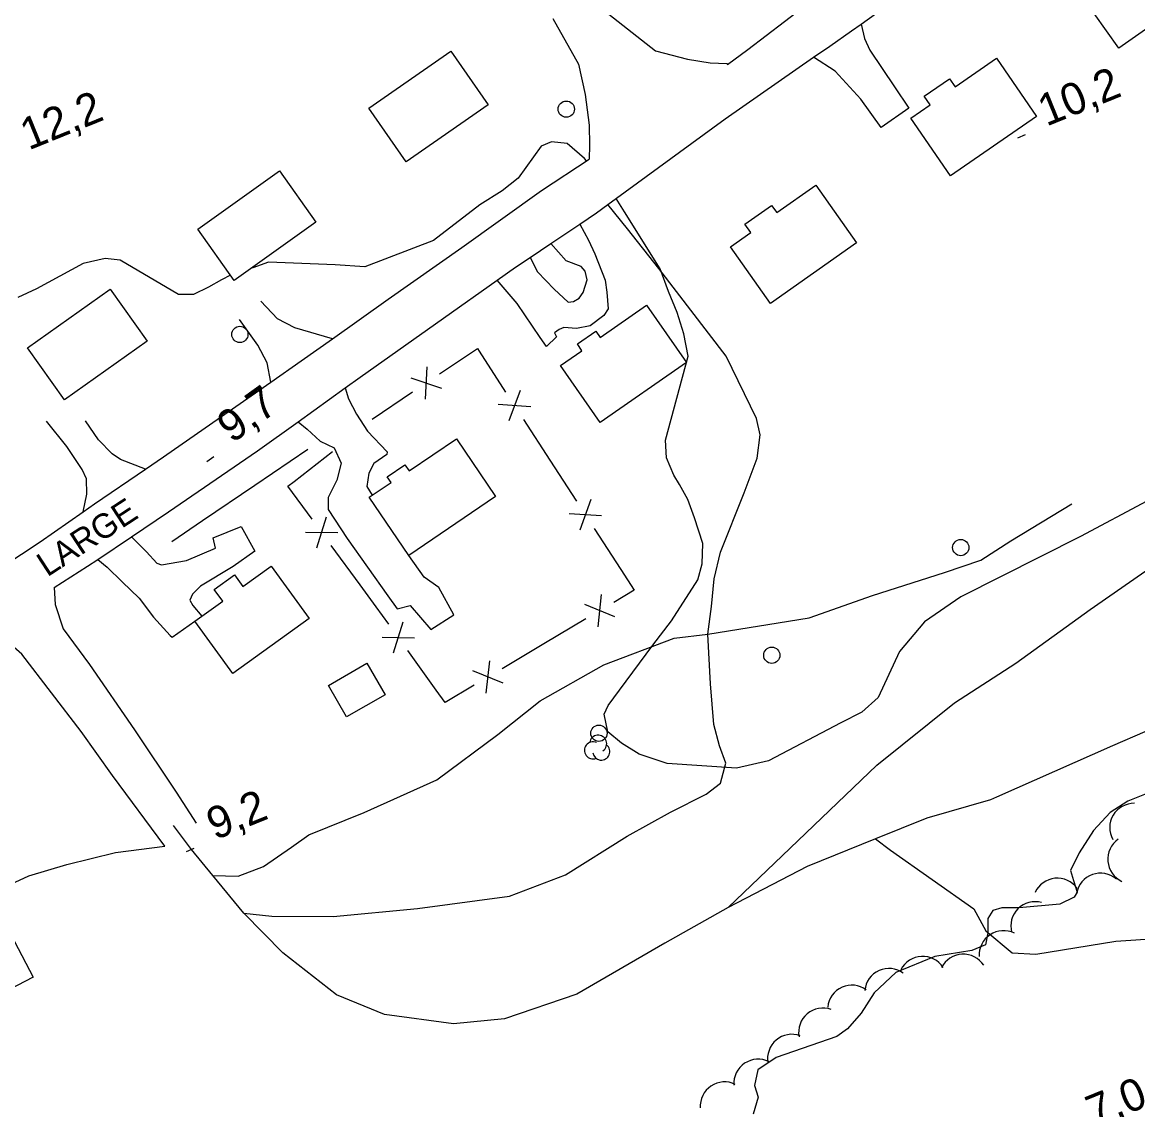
# Model space of a CAD drawing. Extents: x 362852 to 366875, y 5563573 to 5566479.
# Drawn here: x 365220.3 to 365357.5, y 5564880.3 to 5565014.2 of the extents above; entities that cross this region are included whole.
import ezdxf

# ---------------------------------------------------------------- set-up
doc = ezdxf.new("R2010")
doc.units = 0
for name, color, linetype in [('Niveau 1', 7, 'Continuous'), ('Niveau 19', 7, 'Continuous'), ('Niveau 2', 7, 'Continuous'), ('Niveau 21', 7, 'Continuous'), ('Niveau 22', 7, 'Continuous'), ('Niveau 3', 7, 'Continuous'), ('Niveau 31', 7, 'Continuous'), ('Niveau 36', 7, 'Continuous'), ('Niveau 37', 7, 'Continuous'), ('Niveau 4', 7, 'Continuous'), ('Niveau 44', 7, 'Continuous')]:
    doc.layers.add(name, color=color, linetype=linetype)

msp = doc.modelspace()

# ---------------------------------------------------------------- linework, layer by layer
at = {"layer": 'Niveau 1'}
for points in [[(365289.71, 5564997.1), (365289.45, 5564997.4), (365287.32, 5564999.25), (365285.38, 5564999.45), (365284.1, 5564998.92), (365281.28, 5564994.98), (365279.33, 5564993.43), (365276.59, 5564991.68), (365270.85, 5564987.32), (365262.42, 5564984.08), (365258.75, 5564984.29), (365250.58, 5564984.63), (365248.63, 5564983.94), (365248.47, 5564983.89)], [(365358.63, 5564955.23), (365350.48, 5564950.88), (365335.76, 5564943.45), (365331.3, 5564940.38), (365328.2, 5564936.74), (365325.57, 5564931.06), (365323.58, 5564929.24), (365321.01, 5564927.94), (365312.1, 5564923.26), (365308.14, 5564922.36), (365299.63, 5564922.93), (365296.18, 5564924.1), (365294.02, 5564925.43), (365292.33, 5564926.84), (365291.87, 5564929), (365292.36, 5564930.07), (365293.74, 5564931.95), (365297.88, 5564937.5), (365300.17, 5564940.49), (365303.4, 5564945.55), (365303.95, 5564947.51), (365304.03, 5564950.02), (365302.97, 5564953.17), (365302.16, 5564955.44), (365301.16, 5564957.26), (365300.43, 5564958.44), (365299.56, 5564960.55), (365299.4, 5564962.72), (365302.2, 5564973.05), (365301.69, 5564975.82), (365300.85, 5564978.46), (365299.8, 5564981.01), (365298.77, 5564983.82), (365294.39, 5564990.85), (365293.34, 5564992.46)], [(365245.9, 5564983.03), (365244.79, 5564982.48), (365243.19, 5564981.57), (365241.33, 5564980.67), (365239.48, 5564980.65), (365232.31, 5564984.87), (365230.48, 5564985.1), (365227.77, 5564984.48), (365222.01, 5564981.35), (365219.73, 5564980.28)]]:
    msp.add_lwpolyline(points, dxfattribs=at)
at = {"layer": 'Niveau 19'}
for points in [[(365323.48, 5565013.92), (365323.91, 5565012.18), (365324.58, 5565010.72), (365327.61, 5565006.22), (365329.38, 5565003.59), (365325.95, 5565001.2), (365323.45, 5565004.71), (365320.3, 5565008.13), (365317.65, 5565009.85)], [(365288.89, 5564989.33), (365289.95, 5564987.34), (365290.71, 5564985.66), (365291.98, 5564982.41), (365292.21, 5564980.95), (365292.37, 5564978.9), (365291.84, 5564978.06), (365290.13, 5564976.8), (365288.46, 5564976.46), (365286.92, 5564976.58), (365286.34, 5564976.34), (365285.76, 5564975.92), (365286.01, 5564975.46), (365284.77, 5564974.26), (365284, 5564975.37), (365281.16, 5564979.54), (365278.7, 5564982.42)], [(365282.75, 5564985.22), (365283.66, 5564983.44), (365285.72, 5564981.31), (365287.43, 5564979.72), (365288.08, 5564979.8), (365288.78, 5564980.21), (365289.3, 5564980.92), (365289.78, 5564982.48), (365289.54, 5564983.51), (365289.04, 5564984.11), (365287.21, 5564984.79), (365285.32, 5564986.94)], [(365258.44, 5564975.21), (365253.8, 5564976.55), (365251.67, 5564977.67), (365249.61, 5564979.83)], [(365250.84, 5564969.86), (365250.4, 5564972.26), (365249.27, 5564974.43), (365246.99, 5564977.57)], [(365259.99, 5564969.16), (365260.43, 5564967.82), (365261.4, 5564965.92), (365262.76, 5564963.84), (365265.18, 5564961.29), (365265.13, 5564960.95), (365263.53, 5564959.86), (365262.9, 5564958.67), (365262.65, 5564957.01), (365263.33, 5564955.96)], [(365227.77, 5564953.92), (365228.21, 5564956.1), (365228.19, 5564957.96), (365227.65, 5564959.11), (365225.75, 5564961.97), (365223.24, 5564965.06)], [(365235.43, 5564959.17), (365232.36, 5564960.36), (365231.33, 5564961.06), (365229.65, 5564962.75), (365228.06, 5564965.1)], [(365254.2, 5564964.99), (365255.32, 5564964.08), (365256.91, 5564962.62), (365258.63, 5564961.79), (365259.49, 5564959.88), (365258.97, 5564957.82), (365257.91, 5564955.69), (365257.91, 5564954.21), (365260.25, 5564950.61), (365265.25, 5564943.59), (365266.4, 5564941.99), (365267.98, 5564942.37), (365270.55, 5564939.43), (365273.36, 5564941.23), (365271.54, 5564944.61), (365269.72, 5564945.85), (365267.82, 5564948.53)], [(365233.72, 5564950.85), (365235.54, 5564949), (365236.81, 5564947.59), (365237.39, 5564947.39), (365240.47, 5564947.93), (365244.03, 5564949.42), (365243.77, 5564950.7), (365247.2, 5564952.12), (365248.9, 5564949.05), (365246.21, 5564947.19), (365242.2, 5564944.76), (365241.2, 5564943.76), (365240.89, 5564943.02), (365241.27, 5564942.37), (365242.35, 5564941.05)], [(365229.56, 5564948.06), (365230.72, 5564947.09), (365232.57, 5564945.29), (365234.64, 5564943.29), (365236.43, 5564940.94), (365238.46, 5564938.7), (365238.73, 5564938.5), (365241.51, 5564940.44)]]:
    msp.add_lwpolyline(points, dxfattribs=at)
at = {"layer": 'Niveau 2'}
for points in [[(365358.56, 5564919.21), (365356.32, 5564918.29), (365354.15, 5564916.9), (365352.08, 5564914.67), (365350.33, 5564911.96), (365349.24, 5564909.77), (365349.62, 5564908.55), (365350.08, 5564907.12), (365349.72, 5564906.48), (365347.96, 5564905.63), (365342.92, 5564905.17), (365340.8, 5564905.18), (365339.69, 5564904.84), (365339.1, 5564903.85), (365339.08, 5564902.1), (365338.81, 5564900.62), (365337.11, 5564899.92), (365332.56, 5564899.17)], [(365332.56, 5564899.17), (365327.77, 5564897.2), (365325.08, 5564894.73), (365323.51, 5564892.22), (365321.83, 5564890.28), (365320.49, 5564889.35), (365313.02, 5564886.76), (365310.8, 5564885.22), (365310.36, 5564883.3), (365310.82, 5564881.88), (365310.21, 5564879.76)]]:
    msp.add_lwpolyline(points, dxfattribs=at)
at = {"layer": 'Niveau 21'}
for points in [[(365285.08, 5565081.04), (365274.23, 5565073.76), (365264.25, 5565066.33), (365262.74, 5565063.66), (365262.37, 5565059.28), (365262.63, 5565055.78), (365262.96, 5565053.44), (365266.2, 5565050.64), (365272.79, 5565042.14), (365278.74, 5565032.8), (365285.16, 5565024.41), (365288.88, 5565019.54), (365291.87, 5565015.62), (365298.19, 5565010.64), (365302.14, 5565009.6), (365304.92, 5565009.15), (365306.98, 5565009.08), (365307.06, 5565008.98)], [(365224.21, 5564944.58), (365228.3, 5564947.21), (365229.56, 5564948.06), (365233.72, 5564950.85), (365238.28, 5564953.91), (365249.22, 5564961.41), (365254.2, 5564964.99), (365259.99, 5564969.16), (365261.85, 5564970.5), (365272.1, 5564977.74), (365278.7, 5564982.42), (365280.95, 5564984.02), (365282.75, 5564985.22), (365285.32, 5564986.94), (365288.89, 5564989.33), (365290.93, 5564990.7), (365292.34, 5564991.73), (365294.47, 5564993.29), (365306.75, 5565002.26), (365317.65, 5565009.85), (365319.65, 5565011.23), (365322.3, 5565013.09), (365323.48, 5565013.92), (365326.29, 5565015.92)], [(365307.06, 5565008.98), (365309.56, 5565010.82), (365316.32, 5565015.99)], [(365285.55, 5565014.61), (365288.72, 5565009.02), (365289.53, 5565005.26), (365290.04, 5565001.49), (365290.06, 5564999.03), (365290.02, 5564997.31)], [(365206.71, 5564939.83), (365222.47, 5564950.23), (365227.77, 5564953.92), (365229.15, 5564954.88), (365235.43, 5564959.17), (365237.64, 5564960.69), (365245.62, 5564966.22), (365250.84, 5564969.86), (365254.6, 5564972.48), (365258.44, 5564975.21), (365265.31, 5564980.09), (365274.37, 5564986.46), (365284.16, 5564993.44), (365290.02, 5564997.31)], [(365224.21, 5564944.58), (365224.32, 5564942.5), (365225.31, 5564939.5), (365228.53, 5564935.12), (365234.06, 5564927.09), (365239.2, 5564919.41), (365241.65, 5564915.58)], [(365237.8, 5564912.75), (365231.38, 5564921.46), (365227.53, 5564926.89), (365220.22, 5564936.38), (365217.9, 5564938.4), (365215.9, 5564939.16)]]:
    msp.add_lwpolyline(points, dxfattribs=at)
at = {"layer": 'Niveau 22'}
for points in [[(365307.13, 5564905.2), (365314.75, 5564912.51), (365325.41, 5564922.72), (365334.99, 5564930.42), (365342.51, 5564935.28), (365351.66, 5564941.88), (365362.84, 5564949.63), (365373.91, 5564956.4), (365386.19, 5564963.13), (365396.63, 5564969.48), (365400.83, 5564972.05), (365409.66, 5564978.32), (365416.18, 5564982.67), (365419.41, 5564986.44), (365424.14, 5564990.02), (365429.48, 5564993.8), (365434.1, 5564997.76)], [(365247.53, 5564904.52), (365250.96, 5564904.16), (365258.51, 5564904.12), (365268.91, 5564905.09), (365280.23, 5564906.59), (365287.1, 5564909.23), (365294.72, 5564914), (365300.05, 5564916.95), (365304.43, 5564919.17), (365306.17, 5564920.53), (365306.86, 5564922.99), (365306.06, 5564925.09), (365305.35, 5564927.72), (365304.97, 5564932.72), (365304.62, 5564938.85), (365305.09, 5564942.26), (365305.42, 5564945.67), (365306.18, 5564948.94), (365309.09, 5564956.23), (365310.69, 5564960.5), (365311.06, 5564963.38), (365310.6, 5564965.39), (365306.89, 5564973.05), (365298.59, 5564983.87), (365294.76, 5564988.72), (365292.34, 5564991.73)], [(365243.71, 5564909.15), (365246.83, 5564909.07), (365249.94, 5564910.25), (365253.39, 5564912.64), (365255.51, 5564914.16), (365262.32, 5564916.91), (365271.3, 5564920.92), (365278.77, 5564926.5), (365283.98, 5564930.66), (365291.82, 5564935.07), (365300.47, 5564938.38), (365304.62, 5564938.85), (365317.1, 5564940.85), (365324.91, 5564943.61), (365333.75, 5564946.44), (365338.22, 5564947.97), (365341.91, 5564950.32), (365349.41, 5564954.89)], [(365362.38, 5564928.57), (365354.42, 5564925.09), (365340.15, 5564918.79), (365339.41, 5564918.48), (365331.57, 5564916.22), (365325.28, 5564913.67), (365316.87, 5564910.24), (365307.13, 5564905.2), (365299.35, 5564900.82), (365288.5, 5564894.53), (365279.6, 5564891.53), (365273.33, 5564890.88), (365264.85, 5564892.04), (365258.94, 5564894.46), (365252.33, 5564899.62), (365247.53, 5564904.52), (365243.71, 5564909.15), (365241.09, 5564912.34), (365238.86, 5564915.32)], [(365325.28, 5564913.67), (365327.1, 5564912.26), (365337.36, 5564905.05), (365338.84, 5564902.35), (365342.06, 5564899.62), (365344.98, 5564899.47), (365354.85, 5564901.07), (365366.43, 5564901.85), (365373.34, 5564903.41), (365381.11, 5564905.01), (365384.37, 5564906.09), (365387.73, 5564906.92), (365391.49, 5564907.12), (365395.34, 5564907.11)], [(365175.14, 5564901.9), (365175.87, 5564900.77), (365178.83, 5564897.7), (365180.42, 5564895.95), (365182.45, 5564894.49), (365184.59, 5564893.95), (365187.56, 5564894.36), (365190.17, 5564895.25), (365194.98, 5564898.42), (365198.28, 5564899.72), (365203.24, 5564901.78), (365206.61, 5564902.61), (365211.35, 5564904), (365213.52, 5564904.59), (365217.78, 5564907.61), (365221.07, 5564909.1), (365225.75, 5564910.5), (365231.74, 5564912), (365237.8, 5564912.75)]]:
    msp.add_lwpolyline(points, dxfattribs=at)
at = {"layer": 'Niveau 3'}
for p, q in [((365342.77, 5564999.94), (365343.73, 5565000.33)), ((365242.97, 5564960.12), (365243.82, 5564960.73)), ((365240.47, 5564912.11), (365241.43, 5564912.5))]:
    msp.add_line(p, q, dxfattribs=at)
at = {"layer": 'Niveau 31'}
for points in [[(365355.2, 5565010.98), (365350.67, 5565017.43), (365360.8, 5565024.55), (365365.34, 5565018.11), (365355.2, 5565010.98)], [(365262.93, 5565003.58), (365273.02, 5565010.59), (365277.59, 5565004.01), (365267.49, 5564997), (365262.93, 5565003.58), (365262.93, 5565003.58)], [(365345.09, 5565002.58), (365334.47, 5564995.26), (365329.59, 5565002.35), (365331.98, 5565004), (365331.25, 5565005.06), (365334.36, 5565007.21), (365335.05, 5565006.21), (365340.16, 5565009.73), (365345.09, 5565002.58)], [(365256.41, 5564989.57), (365246.36, 5564982.38), (365241.85, 5564988.69), (365251.9, 5564995.88), (365256.41, 5564989.57)], [(365322.93, 5564987), (365312.33, 5564979.55), (365307.41, 5564986.54), (365309.91, 5564988.3), (365309.19, 5564989.33), (365312.47, 5564991.63), (365313.1, 5564990.73), (365317.93, 5564994.12), (365322.93, 5564987)], [(365235.65, 5564974.92), (365225.45, 5564967.68), (365220.91, 5564974.08), (365231.1, 5564981.32), (365235.65, 5564974.92)], [(365265.17, 5564958.22), (365267.35, 5564959.7), (365267.86, 5564958.94), (365273.68, 5564962.89), (365278.5, 5564955.8), (365267.82, 5564948.53), (365262.95, 5564955.7), (365265.64, 5564957.53), (365265.17, 5564958.22)], [(365247.42, 5564944.73), (365250.89, 5564947.24), (365255.55, 5564940.8), (365246.16, 5564934.01), (365241.51, 5564940.44), (365244.95, 5564942.93), (365243.9, 5564944.37), (365246.38, 5564946.17), (365247.42, 5564944.73)], [(365264.92, 5564931.39), (365260.18, 5564928.66), (365257.94, 5564932.55), (365262.68, 5564935.28), (365264.92, 5564931.39)], [(365217.77, 5564894.63), (365215.47, 5564899.03), (365219.33, 5564901.04), (365221.62, 5564896.64), (365217.77, 5564894.63)]]:
    msp.add_lwpolyline(points, dxfattribs=at)
msp.add_lwpolyline([(365291.37, 5564975.38), (365297.1, 5564979.35), (365302, 5564972.28), (365291.37, 5564964.91), (365286.51, 5564971.92), (365289.14, 5564973.74), (365288.57, 5564974.58), (365290.84, 5564976.15), (365291.37, 5564975.38)], close=True, dxfattribs=at)
at = {"layer": 'Niveau 36'}
for centre in [(365287.21, 5565003.47), (365247.04, 5564975.74), (365335.75, 5564949.51), (365312.5, 5564936.26), (365291.22, 5564926.66)]:
    msp.add_circle(centre, 1, dxfattribs=at)
at = {"layer": 'Niveau 37'}
for p, q in [((365276.49, 5564973.68), (365279.75, 5564968.64)), ((365270.06, 5564971.76), (365269.86, 5564967.77)), ((365268.07, 5564970.42), (365271.85, 5564969.11)), ((365263.32, 5564965.31), (365268.3, 5564968.66)), ((365281.53, 5564968.84), (365280.15, 5564965.09)), ((365282.83, 5564966.83), (365278.84, 5564967.1)), ((365281.93, 5564965.29), (365285.2, 5564960.25)), ((365253.71, 5564957.65), (365258.43, 5564961.35)), ((365285.2, 5564960.25), (365288.46, 5564955.22)), ((365290.23, 5564955.42), (365288.86, 5564951.67)), ((365256.53, 5564949.46), (365257.69, 5564953.29)), ((365291.54, 5564953.41), (365287.55, 5564953.68)), ((365290.64, 5564951.86), (365293.91, 5564946.83)), ((365255.11, 5564951.4), (365259.11, 5564951.35)), ((365261.83, 5564944.92), (365258.29, 5564949.76)), ((365291.13, 5564939.76), (365291.56, 5564943.73)), ((365293.19, 5564940.98), (365289.5, 5564942.51)), ((365289.62, 5564940.72), (365284.46, 5564937.66)), ((365265.94, 5564936.54), (365267.13, 5564940.36)), ((365264.54, 5564938.48), (365268.54, 5564938.41)), ((365271.21, 5564931.96), (365267.7, 5564936.83)), ((365284.46, 5564937.66), (365279.3, 5564934.6)), ((365277.37, 5564931.6), (365277.8, 5564935.57)), ((365279.43, 5564932.82), (365275.73, 5564934.35))]:
    msp.add_line(p, q, dxfattribs=at)
for points in [[(365271.62, 5564970.89), (365276.27, 5564974.01), (365276.49, 5564973.68)], [(365255.92, 5564952.99), (365252.95, 5564957.05), (365253.71, 5564957.65)], [(365293.91, 5564946.83), (365295.58, 5564944.25), (365293.07, 5564942.76)], [(365265.36, 5564940.07), (365263.82, 5564942.21), (365261.83, 5564944.92)], [(365275.86, 5564932.56), (365272.3, 5564930.45), (365271.21, 5564931.96)]]:
    msp.add_lwpolyline(points, dxfattribs=at)
at = {"layer": 'Niveau 4'}
msp.add_lwpolyline([(365238.69, 5564950.26), (365242.44, 5564952.85), (365248.88, 5564957.19), (365255.4, 5564961.64)], dxfattribs=at)
at = {"layer": 'Niveau 44'}
for centre, radius, start, end in [((365290.49, 5564924.55), 1.05, 66.2054, 291.894), ((365291.13, 5564925.37), 1.05, 304.3592, 171.8163), ((365291.52, 5564924.4), 1.05, 189.0269, 51.7112), ((365357.08, 5564915.04), 3, 89.2859, 209.2638), ((365356.85, 5564911.15), 3, 124.9961, 244.974), ((365352.95, 5564906.43), 3, 49.5341, 169.512), ((365347.63, 5564905.82), 3, 35.5989, 155.5769), ((365344.91, 5564902.93), 3, 74.9279, 194.9058), ((365341.01, 5564899.36), 3, 63.519, 183.4969), ((365336.06, 5564896.46), 3, 33.0529, 153.0308), ((365331.06, 5564896.2), 3, 33.0529, 153.0308), ((365326.93, 5564894.71), 3, 54.2082, 174.1862), ((365322.37, 5564892.66), 3, 54.2082, 174.1862), ((365318.8, 5564889.84), 3, 70.3582, 190.3362), ((365314.98, 5564886.61), 3, 70.3582, 190.3362), ((365310.83, 5564883.55), 3, 64.0251, 184.003), ((365306.69, 5564880.75), 3, 64.0251, 184.003)]:
    msp.add_arc(centre, radius, start, end, dxfattribs=at)

# ---------------------------------------------------------------- texts
at = {"layer": 'Niveau 21'}
msp.add_text('LARGE', height=3, rotation=33.1112, dxfattribs=at).set_placement((365223.34, 5564945.83))
at = {"layer": 'Niveau 3'}
for s, rotation, p in [('10,2 ', 22.09, (365346.28, 5565001.3)), ('12,2 ', 22.09, (365221.05, 5564998.37)), ('9,7  ', 35.5902, (365246.07, 5564962.26)), ('9,2  ', 22.09, (365243.98, 5564913.47)), ('7,0  ', 22.09, (365352.2, 5564878.11))]:
    msp.add_text(s, height=3.93, rotation=rotation, dxfattribs=at).set_placement(p)

doc.saveas('drawing.dxf')
